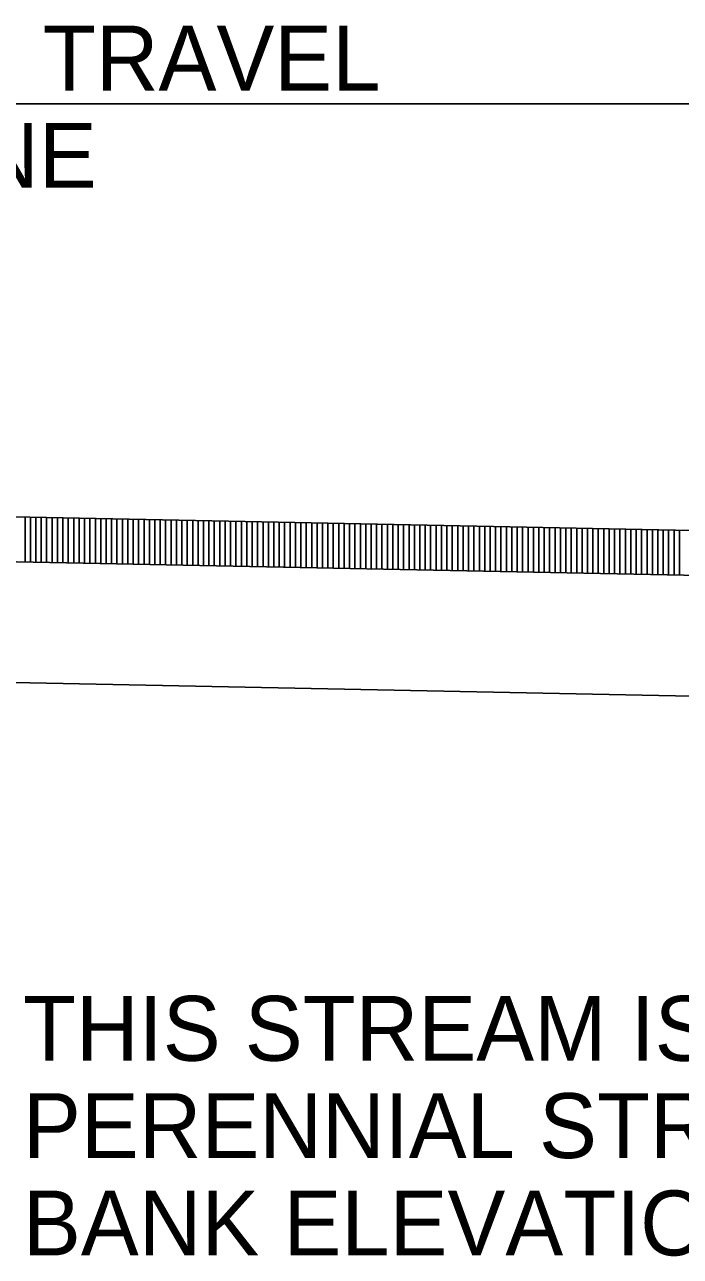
# Model space of a CAD drawing. Extents: x 3575 to 11445, y 9479 to 13278.
# Drawn here: x 7034.1 to 7094.7, y 10423.6 to 10537.5 of the extents above; entities that cross this region are included whole.
import ezdxf

# ---------------------------------------------------------------- set-up
doc = ezdxf.new("R2010")
doc.units = 0
for name, color, linetype in [('ACHM Surface', 7, 'Continuous'), ('Default', 7, 'Continuous'), ('R_Dimension', 7, 'Continuous'), ('STAMP_PE_CRAFTON-SIGNATURE', 7, 'Continuous')]:
    doc.layers.add(name, color=color, linetype=linetype)

msp = doc.modelspace()

# ---------------------------------------------------------------- linework, layer by layer
at = {"layer": 'ACHM Surface'}
for p, q in [((7034.14, 10487.82), (7034.14, 10491.99)), ((7034.64, 10487.81), (7034.64, 10491.98)), ((7035.14, 10487.8), (7035.14, 10491.97)), ((7035.64, 10487.79), (7035.64, 10491.96)), ((7036.14, 10487.78), (7036.14, 10491.95)), ((7036.64, 10487.77), (7036.64, 10491.94)), ((7037.14, 10487.76), (7037.14, 10491.93)), ((7037.64, 10487.75), (7037.64, 10491.92)), ((7038.14, 10487.74), (7038.14, 10491.91)), ((7038.64, 10487.73), (7038.64, 10491.9)), ((7039.14, 10487.72), (7039.14, 10491.89)), ((7039.64, 10487.71), (7039.64, 10491.88)), ((7040.14, 10487.7), (7040.14, 10491.87)), ((7040.64, 10487.69), (7040.64, 10491.86)), ((7041.14, 10487.68), (7041.14, 10491.85)), ((7041.64, 10487.67), (7041.64, 10491.84)), ((7042.14, 10487.66), (7042.14, 10491.83)), ((7042.64, 10487.65), (7042.64, 10491.82)), ((7043.14, 10487.64), (7043.14, 10491.81)), ((7043.64, 10487.63), (7043.64, 10491.8)), ((7044.14, 10487.62), (7044.14, 10491.79)), ((7044.64, 10487.61), (7044.64, 10491.78)), ((7045.14, 10487.6), (7045.14, 10491.77)), ((7045.64, 10487.59), (7045.64, 10491.76)), ((7046.14, 10487.58), (7046.14, 10491.75)), ((7046.64, 10487.57), (7046.64, 10491.74)), ((7047.14, 10487.56), (7047.14, 10491.73)), ((7047.64, 10487.55), (7047.64, 10491.72)), ((7048.14, 10487.54), (7048.14, 10491.71)), ((7048.64, 10487.53), (7048.64, 10491.7)), ((7049.14, 10487.52), (7049.14, 10491.69)), ((7049.64, 10487.51), (7049.64, 10491.68)), ((7050.14, 10487.5), (7050.14, 10491.67)), ((7050.64, 10487.49), (7050.64, 10491.66)), ((7051.14, 10487.48), (7051.14, 10491.65)), ((7051.64, 10487.47), (7051.64, 10491.64)), ((7052.14, 10487.46), (7052.14, 10491.63)), ((7052.64, 10487.45), (7052.64, 10491.62)), ((7053.14, 10487.44), (7053.14, 10491.61)), ((7053.64, 10487.43), (7053.64, 10491.6)), ((7054.14, 10487.42), (7054.14, 10491.59)), ((7054.64, 10487.41), (7054.64, 10491.58)), ((7055.14, 10487.4), (7055.14, 10491.57)), ((7055.64, 10487.39), (7055.64, 10491.56)), ((7056.14, 10487.38), (7056.14, 10491.55)), ((7056.64, 10487.37), (7056.64, 10491.54)), ((7057.14, 10487.36), (7057.14, 10491.53)), ((7057.64, 10487.35), (7057.64, 10491.52)), ((7058.14, 10487.34), (7058.14, 10491.51)), ((7058.64, 10487.33), (7058.64, 10491.5)), ((7059.14, 10487.32), (7059.14, 10491.49)), ((7059.64, 10487.31), (7059.64, 10491.48)), ((7060.14, 10487.3), (7060.14, 10491.47)), ((7060.64, 10487.29), (7060.64, 10491.46)), ((7061.14, 10487.28), (7061.14, 10491.45)), ((7061.64, 10487.27), (7061.64, 10491.44)), ((7062.14, 10487.26), (7062.14, 10491.43)), ((7062.64, 10487.25), (7062.64, 10491.42)), ((7063.14, 10487.24), (7063.14, 10491.41)), ((7063.64, 10487.23), (7063.64, 10491.4)), ((7064.14, 10487.22), (7064.14, 10491.39)), ((7064.64, 10487.21), (7064.64, 10491.38)), ((7065.14, 10487.2), (7065.14, 10491.37)), ((7065.64, 10487.19), (7065.64, 10491.36)), ((7066.14, 10487.18), (7066.14, 10491.35)), ((7066.64, 10487.17), (7066.64, 10491.34)), ((7067.14, 10487.16), (7067.14, 10491.33)), ((7067.64, 10487.15), (7067.64, 10491.32)), ((7068.14, 10487.14), (7068.14, 10491.31)), ((7068.64, 10487.13), (7068.64, 10491.3)), ((7069.14, 10487.12), (7069.14, 10491.29)), ((7069.64, 10487.11), (7069.64, 10491.28)), ((7070.14, 10487.1), (7070.14, 10491.27)), ((7070.64, 10487.09), (7070.64, 10491.26)), ((7071.14, 10487.08), (7071.14, 10491.25)), ((7071.64, 10487.07), (7071.64, 10491.24)), ((7072.14, 10487.06), (7072.14, 10491.23)), ((7072.64, 10487.05), (7072.64, 10491.22)), ((7073.14, 10487.04), (7073.14, 10491.21)), ((7073.64, 10487.03), (7073.64, 10491.2)), ((7074.14, 10487.02), (7074.14, 10491.19)), ((7074.64, 10487.01), (7074.64, 10491.18)), ((7075.14, 10487), (7075.14, 10491.17)), ((7075.64, 10486.99), (7075.64, 10491.16)), ((7076.14, 10486.98), (7076.14, 10491.15)), ((7076.64, 10486.97), (7076.64, 10491.14)), ((7077.14, 10486.96), (7077.14, 10491.13)), ((7077.64, 10486.95), (7077.64, 10491.12)), ((7078.14, 10486.94), (7078.14, 10491.11)), ((7078.64, 10486.93), (7078.64, 10491.1)), ((7079.14, 10486.92), (7079.14, 10491.09)), ((7079.64, 10486.91), (7079.64, 10491.08)), ((7080.14, 10486.9), (7080.14, 10491.07)), ((7080.64, 10486.89), (7080.64, 10491.06)), ((7081.14, 10486.88), (7081.14, 10491.05)), ((7081.64, 10486.87), (7081.64, 10491.04)), ((7082.14, 10486.86), (7082.14, 10491.03)), ((7082.64, 10486.85), (7082.64, 10491.02)), ((7083.14, 10486.84), (7083.14, 10491.01)), ((7083.64, 10486.83), (7083.64, 10491)), ((7084.14, 10486.82), (7084.14, 10490.99)), ((7084.64, 10486.81), (7084.64, 10490.98)), ((7085.14, 10486.8), (7085.14, 10490.97)), ((7085.64, 10486.79), (7085.64, 10490.96)), ((7086.14, 10486.78), (7086.14, 10490.95)), ((7086.64, 10486.77), (7086.64, 10490.94)), ((7087.14, 10486.76), (7087.14, 10490.93)), ((7087.64, 10486.75), (7087.64, 10490.92)), ((7088.14, 10486.74), (7088.14, 10490.91)), ((7088.64, 10486.73), (7088.64, 10490.9)), ((7089.14, 10486.72), (7089.14, 10490.89)), ((7089.64, 10486.71), (7089.64, 10490.88)), ((7090.14, 10486.7), (7090.14, 10490.87)), ((7090.64, 10486.69), (7090.64, 10490.86)), ((7091.14, 10486.68), (7091.14, 10490.85)), ((7091.64, 10486.67), (7091.64, 10490.84)), ((7092.14, 10486.66), (7092.14, 10490.83)), ((7092.64, 10486.65), (7092.64, 10490.82)), ((7093.14, 10486.64), (7093.14, 10490.81)), ((7093.64, 10486.63), (7093.64, 10490.8)), ((7094.14, 10486.62), (7094.14, 10490.79)), ((7094.64, 10486.61), (7094.64, 10490.78))]:
    msp.add_line(p, q, dxfattribs=at)
at = {"layer": 'Default'}
for p, q in [((6994.78, 10492.77), (7104.76, 10490.57)), ((6994.57, 10477.44), (7191.12, 10473.51))]:
    msp.add_line(p, q, dxfattribs=at)
msp.add_lwpolyline([(6994.75, 10488.61), (7095.05, 10486.6), (7104.19, 10486.42), (7125.63, 10485.57), (7144.81, 10484.84)], dxfattribs=at)
at = {"layer": 'R_Dimension'}
msp.add_line((6884.8, 10530.19), (7104.8, 10530.19), dxfattribs=at)

# ---------------------------------------------------------------- texts
for s, p in [('10\'-0" TRAVEL ', (7013.12, 10531.43)), ('   LANE', (7013.12, 10522.43))]:
    msp.add_text(s, height=6, dxfattribs=at).set_placement(p)
at = {"layer": 'STAMP_PE_CRAFTON-SIGNATURE'}
for s, p in [('THIS STREAM IS CLASSIFIED AS A ', (7033.95, 10441.69)), ('PERENNIAL STREAM.  THE STREAM ', (7033.95, 10432.69)), ('BANK ELEVATION IS 345 FT. MSL.', (7033.95, 10423.69))]:
    msp.add_text(s, height=6, dxfattribs=at).set_placement(p)

doc.saveas('drawing.dxf')
